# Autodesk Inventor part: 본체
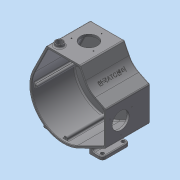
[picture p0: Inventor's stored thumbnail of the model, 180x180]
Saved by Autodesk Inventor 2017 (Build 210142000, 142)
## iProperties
Created: 2017-05
Part Number: 본체
Material: 알루미늄 6061
Document SubType Name: Modeling
Designer: mduedu
Density: 2.71 g/cm^3
Appearance: 기본값
Author: mduedu
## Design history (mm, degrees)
sketch "스케치1"
  geometry: L1 (-71.801, 35.28)-(-40, 100); L2 (-40, 100)-(40, 100); L3 (40, 100)-(59.768, 59.768); L4 (59.768, 59.768)-(100, 40); L5 (100, 40)-(100, -40); L6 (100, -40)-(35.28, -71.801); A1 r 80 centre (0, 0) between (-71.801, 35.28) and (35.28, -71.801); 3 further points
  constraints: 12 end point, 4 tangent, 2 midpoint, 2 point on circle, 1 centre point, 1 coincident, 1 horizontal, 1 horizontal alignment, 1 perpendicular, 1 vertical alignment
  dimensions: "d0" = 160 diameter of A1; "d2" = 100 distance from line of L2 point (0, 0); "d3" = 100 distance from line of L5 point (0, 0); "d4" = 80 distance of L1.end L2.end; "d5" = 80 distance of L4.end L5.end
extrude "돌출1" new body sketch "스케치1" distance "d6" = 5; taper "d7" = 0 deg
fillet "모깎기1" dims "d8" = 50
sketch "스케치2"
  geometry: C1 r 22 at (0, 0); 1 further point
  constraints: 1 centre point, 1 coincident
  dimensions: "d9" = 44 diameter of C1
extrude "돌출2" join sketch "스케치2" distance "d10" = 22.5; taper "d11" = 0 deg
sketch "스케치3"
  geometry: C1 r 18.5 at (0, 0); 1 further point
  constraints: 1 centre point, 1 coincident
  dimensions: "d12" = 37 diameter of C1
extrude "돌출3" cut sketch "스케치3" distance "d13" = 9; taper "d14" = 0 deg
fillet "모깎기2" dims "d15" = 3
sketch "스케치4"
  geometry: L1 (35.28, -71.801)-(100, -40) reference; L2 (100, -40)-(100, 40) reference; L3 (100, 40)-(75.073, 52.248) reference; L4 (52.248, 75.073)-(40, 100) reference; L5 (40, 100)-(-40, 100) reference; L6 (-40, 100)-(-71.801, 35.28) reference; L7 (-36.886, 95)-(36.886, 95); L8 (36.886, 95)-(47.76, 72.868); L9 (72.868, 47.76)-(95, 36.886); L10 (95, 36.886)-(95, -36.886); L11 (95, -36.886)-(33.075, -67.313); L12 (-67.313, 33.075)-(-36.886, 95); C1 r 25 at (0, 0) reference; A1 r 50 centre (97.123, 97.123) between (52.248, 75.073) and (75.073, 52.248) reference; A2 r 80 centre (0, 0) between (-71.801, 35.28) and (35.28, -71.801) reference; A3 r 55 centre (97.123, 97.123) between (47.76, 72.868) and (72.868, 47.76); A4 r 75 centre (0, 0) between (-67.313, 33.075) and (33.075, -67.313); 1 further point
  constraints: 12 end point, 4 point on circle, 2 centre point, 7 other
  dimensions: "d16" = 5 distance between parallel lines of L7 L5
extrude "돌출4" join sketch "스케치4" distance "d17" = 100; taper "d18" = 0 deg
sketch "스케치5"
  geometry: L1 (80, 0)-(0, 0) reference; C1 r 20 at (40, -45); 2 further points
  constraints: 1 centre point, 1 midpoint, 1 vertical alignment
  dimensions: "d19" = 40 diameter of C1; "d21" = 45 distance from line of C1.centre L1
extrude "돌출5" cut sketch "스케치5" stored distance "d22" = 100; taper "d23" = 0 deg
sketch "스케치6"
  geometry: L1 (0, 0)-(0, -105) reference; L2 (80, -105)-(0, -105) reference; C1 r 9 at (14, -89); 1 further point
  constraints: 1 centre point
  dimensions: "d24" = 18 diameter of C1; "d26" = 14 distance from line of C1.centre L1; "d27" = 16 distance from line of C1.centre L2
extrude "돌출6" join sketch "스케치6" distance "d28" = 7; taper "d29" = 0 deg
hole "구멍1" diameter "d32" = 14; stored, may be unused: countersink angle "d36" = 90 deg, drill point angle "d38" = 118 deg; dims "d33" = 6, "d34" = 4, "d35" = 2, "d37" = 8, "d39" = 10, "d40" = 10
sketch "스케치7"
  geometry: L1 (-105, 0)-(-105, 80) reference; L2 (0, 0)-(0, 80) reference; C1 r 20 at (-70, 40); 2 further points
  constraints: 1 centre point, 1 horizontal alignment, 1 midpoint
  dimensions: "d41" = 40 diameter of C1; "d42" = 35 distance from line of C1.centre L1
extrude "돌출7" cut sketch "스케치7" stored distance "d43" = 7; taper "d44" = 0 deg
node "작업 평면1"
sketch "스케치8"
  geometry: L1 (47.76, 72.868)-(36.886, 95) reference; L2 (36.886, 95)-(-36.886, 95) reference; L3 (-36.886, 95)-(-67.313, 33.075) reference; L4 (33.075, -67.313)-(95, -36.886) reference; L5 (95, -36.886)-(95, 36.886) reference; L6 (95, 36.886)-(72.868, 47.76) reference; L7 (95, 36.886)-(95, -36.886) reference; L8 (-36.886, 95)-(36.886, 95) reference; L9 (36.886, 95)-(47.76, 72.868) reference; L10 (-71, 4)-(-74.893, 4); L11 (-71, -4)-(-74.893, -4); L12 (-4, -71)-(-4, -74.893); L13 (4, -71)-(4, -74.893); L14 (30.394, 91)-(30.394, 95); L15 (34.394, 87)-(40.817, 87); L16 (30.394, 95)-(36.886, 95); L17 (36.886, 95)-(37.984, 92.764); L18 (91, 30.394)-(95, 30.394); L19 (87, 34.394)-(87, 40.817); L20 (87, 40.817)-(95, 36.886); L21 (95, 36.886)-(95, 30.394); C1 r 25 at (0, 0) reference; A1 r 75 centre (0, 0) between (-67.313, 33.075) and (33.075, -67.313) reference; A2 r 55 centre (97.123, 97.123) between (47.76, 72.868) and (72.868, 47.76) reference; A3 r 4 centre (-71, 0) between (-71, 4) and (-71, -4); A4 r 4 centre (0, -71) between (-4, -71) and (4, -71); A5 r 4 centre (34.394, 91) between (30.394, 91) and (34.394, 87); A6 r 75 centre (0, 0) between (-67.313, 33.075) and (33.075, -67.313) reference; A7 r 4 centre (91, 34.394) between (91, 30.394) and (87, 34.394); 1 further point
  constraints: 24 end point, 17 point on circle, 14 tangent, 5 point on line, 4 centre point, 3 equal radius, 3 perpendicular, 3 vertical, 2 collinear, 2 horizontal, 1 horizontal alignment, 1 parallel, 1 vertical alignment
  dimensions: "d46" = 8 diameter of A3
extrude "돌출8" join sketch "스케치8" stored distance "d49" = 7; taper "d50" = 0 deg
node "작업 평면2"
sketch "스케치9"
  geometry: L1 (71.801, 0)-(71.801, 105) reference; L2 (71.801, 0)-(-35.28, 0) reference; L3 (-35.28, 0)-(-35.28, 105) reference; L4 (71.801, 105)-(-35.28, 105) reference; L5 (40, 0)-(40, 105) reference; L6 (71.801, 52.5)-(-35.28, 52.5); L7 (71.801, 20)-(40, 20); L8 (40, 20)-(40, 85); L9 (40, 85)-(71.801, 85); L10 (71.801, 85)-(71.801, 20); 1 further point
  constraints: 10 end point, 2 midpoint, 2 parallel, 2 point on line, 1 horizontal, 1 perpendicular, 1 other
  dimensions: "d52" = 20 distance between parallel lines of L7 L2
extrude "돌출9" join sketch "스케치9" distance "d53" = 8; taper "d54" = 0 deg
fillet "모깎기3" dims "d55" = 8
sketch "스케치10"
  geometry: C1 r 4 at (-63.801, -28); C2 r 4 at (-63.801, -77); A1 r 8 centre (-63.801, -28) between (-63.801, -20) and (-71.801, -28) reference; A2 r 8 centre (-63.801, -77) between (-71.801, -77) and (-63.801, -85) reference; 1 further point
  constraints: 2 centre point, 2 coincident, 1 equal radius
  dimensions: "d56" = 8 diameter of C1
extrude "돌출10" cut sketch "스케치10" stored distance "d57" = 50.5; taper "d58" = 0 deg
sketch "스케치11"
  geometry: L1 (-63.801, -20)-(-40, -20) reference; L2 (-40, -20)-(-40, -85) reference; L3 (-40, -85)-(-63.801, -85) reference; L4 (-71.801, -77)-(-71.801, -28) reference; L5 (71.801, -77)-(71.801, -28) reference; L6 (40, -85)-(63.801, -85) reference; L7 (40, -20)-(40, -85) reference; L8 (63.801, -20)-(40, -20) reference; L9 (-40, -85)-(-48, -85); L10 (-48, -85)-(-48, -20); L11 (-48, -20)-(-40, -20); L12 (-40, -20)-(-40, -85); L13 (40, -85)-(48, -85); L14 (48, -85)-(48, -20); L15 (48, -20)-(40, -20); L16 (40, -20)-(40, -85); C1 r 4 at (-63.801, -28) reference; C2 r 4 at (-63.801, -77) reference; C3 r 4 at (63.801, -28) reference; C4 r 4 at (63.801, -77) reference; A1 r 8 centre (-63.801, -28) between (-63.801, -20) and (-71.801, -28) reference; A2 r 8 centre (-63.801, -77) between (-71.801, -77) and (-63.801, -85) reference; A3 r 8 centre (63.801, -28) between (71.801, -28) and (63.801, -20) reference; A4 r 8 centre (63.801, -77) between (63.801, -85) and (71.801, -77) reference; 1 further point
  constraints: 16 end point, 4 parallel, 2 horizontal, 2 perpendicular, 2 point on line
  dimensions: "d59" = 8 distance of L10.end L11.end; "d61" = 8 distance of L14.end L15.end
extrude "돌출11" join sketch "스케치11" stored distance "d62" = 5; taper "d63" = 0 deg
fillet "모깎기4" dims "d64" = 5
fillet "모깎기5" dims "d65" = 2
fillet "모깎기6" dims "d66" = 2
fillet "모깎기8" dims "d68" = 2
fillet "모깎기9" dims "d70" = 3, "d101" = 1
fillet "모깎기10" dims "d71" = 3
fillet "모깎기11" dims "d72" = 3
fillet "모깎기12" dims "d73" = 3
fillet "모깎기13" dims "d76" = 3
chamfer "모따기1" distance "d77" = 0.5; stored, may be unused: second distance "d78" = 2, angle "d79" = 45 deg
chamfer "모따기2" distance "d87" = 1; stored, may be unused: second distance "d88" = 2, angle "d89" = 45 deg
chamfer "모따기3" distance "d90" = 1; stored, may be unused: second distance "d91" = 2, angle "d92" = 45 deg
sketch "스케치14"
  geometry: 3 further points
  constraints: 3 other
hole "구멍2" sketch "스케치14" at (-55.375, -40), (-3.414, -40), (-29.394, -85) diameter "d93" = 2.459; stored, may be unused: countersink angle "d97" = 90 deg, drill point angle "d99" = 0 deg; dims "d94" = 6, "d95" = 4, "d96" = 2, "d98" = 8
sketch "스케치15"
  geometry: 3 further points
  constraints: 3 other
hole "구멍4" sketch "스케치15" at (-55.981, -14.394), (-4.019, -14.394), (-30, -59.394) diameter "d102" = 2.459; stored, may be unused: countersink angle "d106" = 90 deg, drill point angle "d108" = 0 deg; dims "d103" = 6, "d104" = 4, "d105" = 2, "d107" = 8
sketch "스케치16"
  geometry: 4 further points
  constraints: 4 other
hole "구멍6" sketch "스케치16" at (0, -71), (91, 34.394), (34.394, 91), (-71, 0) diameter "d109" = 2.459; stored, may be unused: countersink angle "d113" = 90 deg, drill point angle "d115" = 120 deg; dims "d110" = 8.5, "d111" = 4, "d112" = 2, "d114" = 10
node "작업 평면4"
sketch "스케치17"
  geometry: 2 further points
  constraints: 1 horizontal alignment, 1 other
  dimensions: "d116" = 52.5 distance of point (0, 16.14) point (52.5, 16.14)
feature "엠보싱2" sketch "스케치17" dims "d117" = 0.5, "d118" = 0
node "솔리드1"
mirror "대칭1"
node "투영된 루프1"
node "투영된 루프2"
node "투영된 루프3"
node "투영된 루프4"
node "투영된 루프5"
other parameters: "d45" = 95
